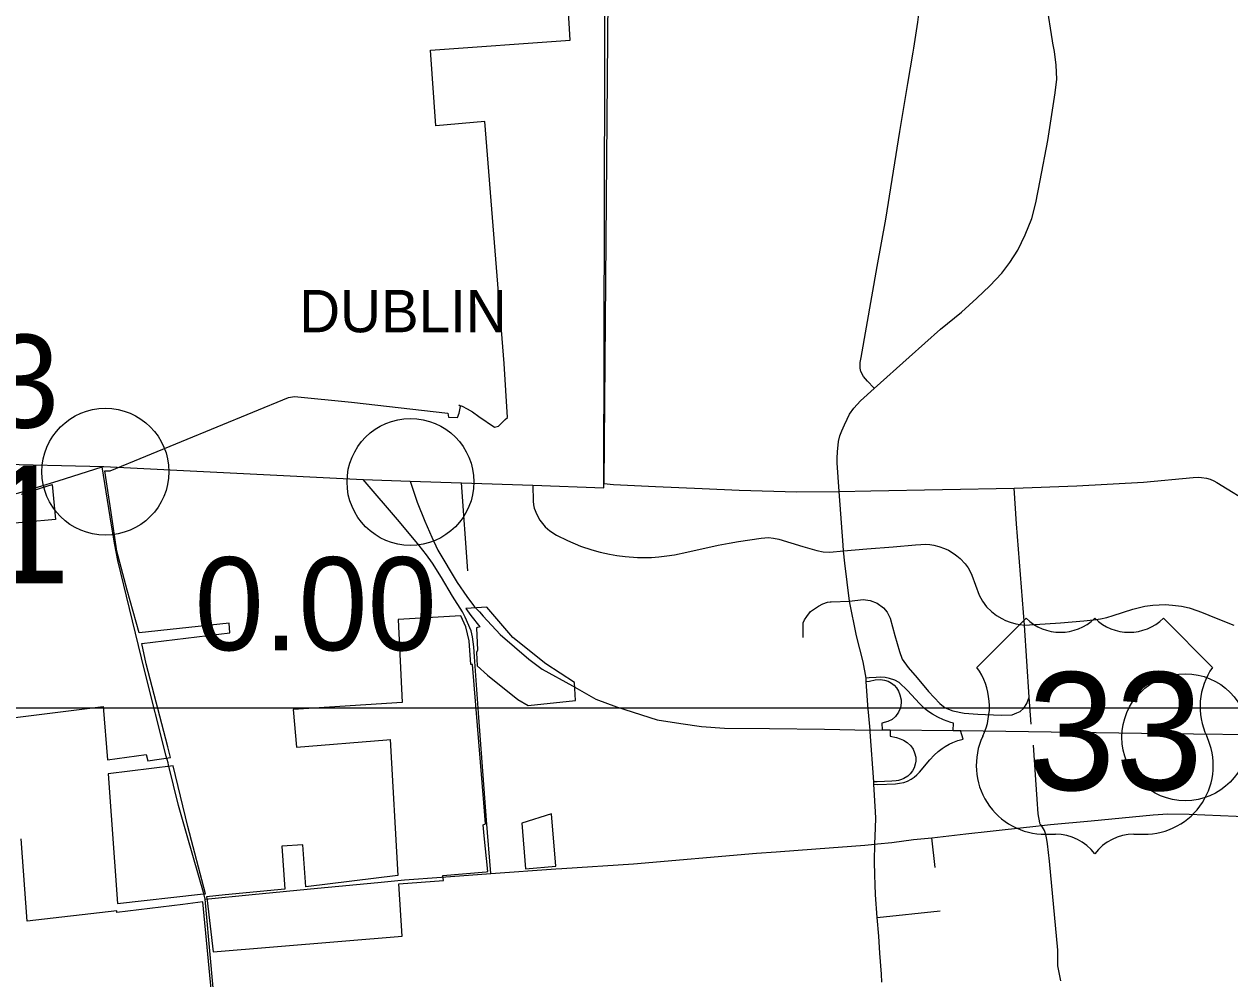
# Model space of a CAD drawing. Extents: x 1729596 to 1934326, y 644115 to 911751.
# Drawn here: x 1774170 to 1788422, y 762296 to 773580 of the extents above; entities that cross this region are included whole.
import ezdxf

# ---------------------------------------------------------------- set-up
doc = ezdxf.new("R2010")
doc.units = 0
for name, color, linetype in [('Default', 7, 'Continuous'), ('GM_X_Adjacent_County', 7, 'Continuous'), ('GM_X_City_Street', 7, 'Continuous'), ('GM_X_Corporation', 7, 'Continuous'), ('GM_X_Corporation_Text', 7, 'Continuous'), ('GM_X_County', 7, 'Continuous'), ('GM_X_County_Road', 7, 'Continuous'), ('GM_X_Interchange_Ramps', 7, 'Continuous'), ('GM_X_State_Route', 7, 'Continuous'), ('GM_X_State_Shield', 7, 'Continuous'), ('GM_X_US_Route', 7, 'Continuous'), ('GM_X_US_Shield', 7, 'Continuous'), ('SC_Scratch1', 7, 'Continuous')]:
    doc.layers.add(name, color=color, linetype=linetype)

msp = doc.modelspace()

# ---------------------------------------------------------------- linework, layer by layer
at = {"layer": 'Default'}
for centre in [(1775131, 768290), (1775131, 768290), (1778737, 768169), (1778737, 768169), (1787895, 765152)]:
    msp.add_circle(centre, 750, dxfattribs=at)
at = {"layer": 'GM_X_Adjacent_County'}
msp.add_line((1781136, 781321), (1781021, 768152), dxfattribs=at)
at = {"layer": 'GM_X_City_Street'}
for points in [[(1784685, 773296), (1784735, 773603), (1784745, 773698), (1784736, 773770), (1784721, 773835), (1784428, 774903), (1784235, 775534), (1784138, 775865), (1784125, 775929), (1784115, 775990), (1784111, 776055), (1784114, 776105), (1784158, 776324), (1784196, 776473), (1784235, 776672), (1784238, 776744), (1784231, 776844), (1784215, 776918), (1784131, 777234), (1783629, 779189), (1783538, 779530), (1783263, 780534), (1783093, 781151)], [(1786330, 773355), (1786325, 773382), (1786259, 773807)], [(1784219, 769275), (1784630, 769643), (1785003, 769974), (1785250, 770175), (1785431, 770342), (1785586, 770486), (1785725, 770636), (1785822, 770764), (1785915, 770909), (1786003, 771088), (1786080, 771284), (1786130, 771467), (1786180, 771733), (1786271, 772205), (1786359, 772769), (1786375, 772928), (1786368, 773096), (1786350, 773256), (1786330, 773355)], [(1784617, 772879), (1784677, 773247), (1784685, 773296)], [(1784213, 769281), (1784139, 769359), (1784090, 769415), (1784062, 769474), (1784054, 769512), (1784054, 769579), (1784065, 769640), (1784254, 770715), (1784357, 771275), (1784523, 772309), (1784617, 772879)], [(1783804, 768056), (1783780, 768394), (1783780, 768450), (1783783, 768525), (1783798, 768648), (1783813, 768714), (1783836, 768775), (1783866, 768846), (1783898, 768910), (1783928, 768970), (1783978, 769042), (1784055, 769126), (1784219, 769275), (1784213, 769281)], [(1779493, 766103), (1779484, 766221), (1779471, 766340), (1779453, 766411), (1779385, 766572), (1779352, 766635), (1779235, 766821), (1779105, 767038), (1778997, 767211), (1778926, 767307), (1778839, 767419), (1778606, 767697), (1778179, 768197)], [(1781021, 768152), (1781136, 768138), (1781634, 768114), (1782186, 768090), (1782622, 768070), (1783303, 768053), (1783804, 768056), (1784178, 768065), (1785871, 768094), (1786614, 768122), (1787402, 768168), (1787989, 768220), (1788050, 768225), (1788088, 768222), (1788147, 768214), (1788188, 768200), (1788232, 768182), (1788269, 768163), (1789144, 767627)], [(1779414, 767119), (1779340, 768157)], [(1780182, 768130), (1780186, 767940), (1780191, 767900), (1780199, 767860), (1780209, 767831), (1780225, 767791), (1780264, 767716), (1780328, 767640), (1780383, 767593), (1780464, 767541), (1780593, 767477), (1780746, 767411), (1780882, 767365), (1780980, 767338), (1781089, 767315), (1781178, 767298), (1781275, 767287), (1781420, 767277), (1781586, 767278), (1781671, 767283), (1781767, 767294), (1781857, 767309), (1782004, 767339), (1782372, 767420), (1782502, 767447), (1782613, 767464), (1782882, 767503), (1782970, 767511), (1783029, 767506), (1783091, 767492), (1783376, 767405), (1783539, 767357), (1783614, 767345), (1783692, 767340), (1783857, 767355)], [(1783852, 767420), (1783804, 768056)], [(1786072, 765306), (1786049, 765627), (1785994, 766475), (1785901, 767676), (1785871, 768094)], [(1784124, 765809), (1784124, 765849), (1784086, 766044), (1784010, 766349), (1783927, 766762), (1783870, 767211), (1783857, 767355), (1783852, 767420)], [(1783857, 767355), (1784133, 767378), (1784442, 767403), (1784707, 767426), (1784770, 767430), (1784829, 767433), (1784875, 767429), (1784924, 767421), (1784983, 767408), (1785048, 767383), (1785097, 767361), (1785164, 767319), (1785196, 767295), (1785235, 767263), (1785294, 767200), (1785327, 767154), (1785353, 767109), (1785372, 767066), (1785457, 766832), (1785497, 766760), (1785547, 766692), (1785604, 766637), (1785664, 766590), (1785727, 766554), (1785772, 766532), (1785825, 766512), (1785893, 766493), (1785994, 766475)], [(1783927, 766762), (1784087, 766780), (1784169, 766769), (1784254, 766735), (1784329, 766680), (1784371, 766630)], [(1783380, 766332), (1783377, 766447), (1783380, 766504), (1783395, 766540), (1783423, 766579), (1783467, 766638), (1783560, 766703), (1783610, 766729), (1783668, 766747), (1783699, 766752)], [(1783699, 766752), (1783711, 766754), (1783927, 766762)], [(1784371, 766630), (1784376, 766624), (1784408, 766561), (1784463, 766354), (1784518, 766165), (1784550, 766075), (1784618, 765975), (1784726, 765853), (1784860, 765691), (1784992, 765549), (1785058, 765499), (1785146, 765465), (1785280, 765436), (1785444, 765424), (1785717, 765413), (1785849, 765415), (1785906, 765439), (1785943, 765457), (1785988, 765495), (1786021, 765551), (1786049, 765627)], [(1785994, 766475), (1786422, 766506), (1786697, 766528), (1786810, 766539), (1786893, 766552), (1786966, 766568), (1787044, 766592), (1787277, 766667), (1787418, 766703), (1787513, 766714), (1787587, 766718), (1787656, 766721), (1787746, 766714), (1787852, 766701), (1787940, 766680), (1788043, 766647), (1788107, 766621), (1788242, 766568), (1788469, 766478)], [(1779685, 763542), (1779637, 764172), (1779545, 765387), (1779493, 766103)], [(1784171, 765217), (1784170, 765235), (1784144, 765530), (1784124, 765809)], [(1784233, 764269), (1784215, 764596), (1784214, 764625), (1784171, 765217)], [(1786194, 764108), (1786181, 764123), (1786174, 764142), (1786157, 764248), (1786146, 764419), (1786127, 764649), (1786100, 765059)], [(1775876, 764825), (1775871, 764848), (1775850, 764928)], [(1784229, 763410), (1784229, 763419), (1784225, 763513), (1784220, 763690), (1784225, 763888), (1784235, 764083), (1784237, 764194), (1784233, 764269)], [(1786194, 764108), (1786301, 764120), (1786784, 764165), (1787517, 764236), (1787687, 764247), (1787940, 764244), (1788496, 764220), (1788942, 764207)], [(1784256, 763891), (1784428, 763910), (1784682, 763942), (1784901, 763964), (1785303, 764011), (1785590, 764041), (1785732, 764058), (1786128, 764102), (1786194, 764108)], [(1786424, 762272), (1786390, 762450), (1786389, 762635), (1786289, 763689), (1786266, 763891), (1786259, 763942), (1786246, 764003), (1786230, 764049), (1786194, 764108)], [(1784937, 763614), (1784901, 763964)], [(1780526, 763602), (1781375, 763657), (1782825, 763782), (1783060, 763799), (1783527, 763834), (1784109, 763878), (1784225, 763888), (1784256, 763891)], [(1779104, 763498), (1779685, 763542), (1780457, 763598), (1780526, 763602)], [(1784308, 762257), (1784306, 762353), (1784284, 762601), (1784271, 762802), (1784255, 763022), (1784234, 763291), (1784229, 763410)], [(1776894, 757007), (1776536, 760730), (1776379, 762498), (1776312, 763238), (1776297, 763289)], [(1784255, 763022), (1784997, 763101)]]:
    msp.add_lwpolyline(points, dxfattribs=at)
at = {"layer": 'GM_X_Corporation'}
for points in [[(1774031, 765380), (1775103, 765517), (1775155, 764887), (1775613, 764948), (1775632, 764875), (1775901, 764913), (1775868, 765038), (1775612, 766018), (1775562, 766261), (1776602, 766385), (1776595, 766499), (1775530, 766385), (1775389, 766892), (1775267, 767351), (1775201, 767808), (1775125, 768301), (1775186, 768299), (1777296, 769167), (1777365, 769179), (1778041, 769112), (1779178, 768980), (1779186, 768933), (1779291, 768930), (1779312, 768982), (1779321, 769021), (1779329, 769061), (1779309, 769075), (1779349, 769065), (1779409, 769034), (1779471, 768997), (1779544, 768942), (1779731, 768815), (1779777, 768829), (1779819, 768873), (1779857, 768907), (1779885, 768930), (1779843, 769567), (1779616, 772429), (1779035, 772377), (1778973, 773273), (1780624, 773390), (1780602, 773789)], [(1774140, 768026), (1774502, 768137), (1774541, 767725), (1773835, 767662)], [(1772730, 760702), (1774189, 760869), (1774141, 761779), (1776402, 761968), (1776281, 763207), (1776046, 763174), (1775267, 763080), (1775267, 763099), (1774207, 762980), (1774134, 763952)]]:
    msp.add_lwpolyline(points, dxfattribs=at)
for points in [[(1779526, 765996), (1779649, 765886), (1780007, 765600), (1780127, 765528), (1780688, 765588), (1780677, 765797), (1780336, 766018), (1779945, 766331), (1779640, 766689), (1779392, 766675), (1779449, 766592), (1779558, 766458), (1779517, 766446), (1779531, 766180), (1779519, 766152)], [(1777350, 765480), (1777390, 765033), (1778456, 765121), (1778497, 765124), (1778588, 763518), (1777500, 763383), (1777464, 763881), (1777215, 763863), (1777251, 763358), (1776548, 763289), (1776325, 763267), (1776334, 763222), (1776405, 762617), (1778638, 762800), (1778601, 763421), (1779128, 763459), (1779121, 763518), (1779630, 763563), (1779650, 763567), (1779608, 763988), (1779595, 764118), (1779623, 764127), (1779603, 764375), (1779472, 766012), (1779452, 766010), (1779430, 766292), (1779392, 766458), (1779331, 766585), (1778592, 766543), (1778640, 765564)], [(1775930, 764813), (1775164, 764721), (1775275, 763188), (1776254, 763296), (1776316, 763302), (1776105, 764098)], [(1780404, 764245), (1780055, 764138), (1780095, 763598), (1780455, 763628)]]:
    msp.add_lwpolyline(points, close=True, dxfattribs=at)
at = {"layer": 'GM_X_County'}
msp.add_lwpolyline([(1773771, 768383), (1775112, 768352), (1778179, 768197), (1778733, 768178), (1779340, 768157), (1780182, 768130), (1781021, 768101), (1781021, 768152), (1781038, 774723), (1781034, 776910), (1781136, 781321), (1783093, 781151), (1784567, 781031), (1785941, 780892), (1786346, 780876), (1788100, 780727), (1790229, 780426)], dxfattribs=at)
at = {"layer": 'GM_X_County_Road'}
for points in [[(1775850, 764928), (1775594, 765946), (1775415, 766673), (1775278, 767240), (1775242, 767424), (1775205, 767658), (1775094, 768346)], [(1776297, 763289), (1776096, 763986), (1775996, 764347), (1775876, 764825)], [(1776312, 763238), (1776864, 763293), (1777637, 763368), (1778352, 763436), (1778667, 763465), (1779104, 763498)]]:
    msp.add_lwpolyline(points, dxfattribs=at)
at = {"layer": 'GM_X_Interchange_Ramps'}
for points in [[(1785153, 765233), (1785154, 765320), (1785124, 765326), (1785036, 765358), (1784970, 765390), (1784907, 765424), (1784851, 765461), (1784810, 765495), (1784755, 765549), (1784613, 765705), (1784512, 765799), (1784462, 765826), (1784398, 765848), (1784348, 765859), (1784295, 765863), (1784240, 765858), (1784159, 765854), (1784124, 765849)], [(1784124, 765809), (1784161, 765815), (1784230, 765832), (1784292, 765836), (1784340, 765828), (1784382, 765814), (1784423, 765791), (1784453, 765767), (1784482, 765734), (1784505, 765698), (1784522, 765654), (1784536, 765596), (1784538, 765557), (1784528, 765501), (1784506, 765449), (1784469, 765398), (1784430, 765363), (1784381, 765338), (1784309, 765320), (1784313, 765239)], [(1784407, 765240), (1784406, 765164), (1784482, 765148), (1784524, 765134), (1784564, 765117), (1784608, 765091), (1784651, 765052), (1784680, 765010), (1784696, 764968), (1784709, 764918), (1784709, 764871), (1784702, 764833), (1784689, 764792), (1784670, 764756), (1784642, 764719), (1784614, 764691), (1784570, 764665), (1784539, 764652), (1784506, 764641), (1784479, 764636), (1784426, 764632), (1784254, 764626), (1784214, 764625)], [(1784215, 764596), (1784263, 764593), (1784470, 764602), (1784518, 764608), (1784567, 764617), (1784610, 764633), (1784654, 764656), (1784690, 764681), (1784722, 764709), (1784752, 764740), (1784875, 764884), (1784926, 764939), (1784976, 764983), (1785023, 765019), (1785056, 765043), (1785106, 765071), (1785147, 765091), (1785206, 765113), (1785270, 765131), (1785239, 765232)]]:
    msp.add_lwpolyline(points, dxfattribs=at)
at = {"layer": 'GM_X_State_Route'}
msp.add_lwpolyline([(1770782, 767754), (1771024, 767766), (1772115, 767838), (1772909, 767883), (1773429, 767916), (1773615, 767939), (1773818, 767968), (1774109, 768040), (1774573, 768184), (1775094, 768346), (1775112, 768352)], dxfattribs=at)
at = {"layer": 'GM_X_US_Route'}
for points in [[(1778733, 768178), (1778817, 767930), (1778905, 767705), (1778988, 767518), (1779062, 767362), (1779287, 766981), (1779404, 766816), (1779481, 766710)], [(1779481, 766710), (1779494, 766693), (1779551, 766633)], [(1779551, 766633), (1779597, 766584), (1779797, 766367), (1780136, 766075), (1780293, 765955), (1780653, 765760), (1780928, 765603), (1781172, 765512), (1781651, 765359), (1781933, 765316), (1782177, 765280), (1782448, 765261), (1782979, 765256)], [(1782979, 765256), (1783630, 765249), (1784170, 765235)], [(1784170, 765235), (1784313, 765239), (1784407, 765240), (1785153, 765233), (1785239, 765232), (1787647, 765195), (1789027, 765180), (1789601, 765171), (1789778, 765169)]]:
    msp.add_lwpolyline(points, dxfattribs=at)
at = {"layer": 'GM_X_US_Shield'}
for p, q in [((1786013, 766558), (1785433, 765978)), ((1788217, 765978), (1787637, 766558)), ((1786245, 764006), (1786361, 764006)), ((1787289, 764006), (1787405, 764006))]:
    msp.add_line(p, q, dxfattribs=at)
for centre, radius, start, end in [((1786419, 766973), 580, 225.573, 314.427), ((1787231, 766973), 580, 225.573, 314.427), ((1784768, 765512), 812, 334.5471, 35.0009), ((1788882, 765512), 812, 144.9991, 205.4529), ((1786236, 764818), 812, 154.8319, 270.6383), ((1787414, 764818), 812, 269.3617, 25.1681), ((1786361, 763426), 580, 36.8699, 90), ((1787289, 763426), 580, 90, 143.1301)]:
    msp.add_arc(centre, radius, start, end, dxfattribs=at)
at = {"layer": 'SC_Scratch1'}
msp.add_lwpolyline([(1729596, 899996), (1925846, 899996), (1925846, 765496), (1729596, 765496)], close=True, dxfattribs=at)

# ---------------------------------------------------------------- texts
at = {"layer": 'Default'}
for s, p in [('0.83', (1771722, 768810)), ('0.00', (1776185, 766180))]:
    msp.add_text(s, height=1100, dxfattribs=at).set_placement(p)
at = {"layer": 'GM_X_Corporation_Text'}
msp.add_text('DUBLIN', height=500, rotation=0, dxfattribs=at).set_placement((1777422, 769938))
at = {"layer": 'GM_X_State_Shield'}
msp.add_text('161', height=1392.2, dxfattribs=at).set_placement((1771610, 766969))
at = {"layer": 'GM_X_US_Shield'}
msp.add_text('33', height=1392.2, dxfattribs=at).set_placement((1786033, 764528))

doc.saveas('drawing.dxf')
